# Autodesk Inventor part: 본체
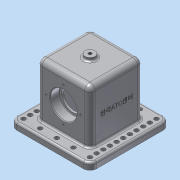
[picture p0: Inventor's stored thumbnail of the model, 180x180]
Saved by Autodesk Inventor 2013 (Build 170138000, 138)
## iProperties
Created: 2018-11
Part Number: 본체
Material: 알루미늄 6061
Document SubType Name: Modeling
Designer: dgall
Density: 2.71 g/cm^3
Mass: 1020.76 g
Surface Area: 777.082 cm^2
Volume: 376.663 cm^3
Author: dgall
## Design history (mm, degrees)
sketch "스케치1"
  geometry: L1 (0, 0)-(80, 0); L2 (80, 0)-(80, 80); L3 (80, 80)-(0, 80); L4 (0, 80)-(0, 0)
  constraints: 8 end point, 2 parallel, 2 perpendicular, 1 horizontal
  dimensions: "d0" = 80 distance of L2.end L3.end
extrude "돌출1" new body sketch "스케치1" distance "d2" = 90; taper "d3" = 0 deg
node "작업 평면1"
sketch "스케치2"
  geometry: L1 (0, 48)-(80, 48); L2 (0, 0)-(0, 90) reference; L3 (80, 0)-(80, 90) reference; L4 (80, 0)-(0, 0) reference; L5 (0, 48)-(0, 68); L6 (0, 68)-(14, 68); L7 (14, 68)-(14, 64.5); L8 (14, 64.5)-(66, 64.5); L9 (66, 64.5)-(66, 68); L10 (66, 68)-(80, 68); L11 (80, 68)-(80, 48)
  constraints: 17 end point, 5 perpendicular, 3 point on line, 1 horizontal
  dimensions: "d4" = 48 distance between parallel lines of L4 L1; "d5" = 40 diameter of L5.end L1; "d6" = 33 diameter of L8 L1; "d7" = 40 diameter of L10.end L1; "d8" = 14 distance of L9.end L10.end; "d9" = 14 distance of L5.end L6.end
revolve "회전1" sketch "스케치2" stored, may be unused: angle "d10" = 90 deg
sketch "스케치3"
  geometry: L1 (-80, 80)-(0, 80) reference; L2 (-80, 0)-(-80, 80) reference; L3 (0, 80)-(0, 0) reference; L4 (-10, 63)-(-10, 17); L5 (-70, 63)-(-70, 17); L6 (-70, 63)-(-10, 63); L7 (-70, 17)-(-10, 17); 6 further points
  constraints: 8 end point, 6 midpoint, 3 parallel, 1 horizontal alignment, 1 perpendicular, 1 vertical alignment
  dimensions: "d91" = 46 distance of L5.start L5.end; "d93" = 60 distance of L5.start L4.start
extrude "돌출2" cut sketch "스케치3" distance "d13" = 80; taper "d14" = 0 deg
node "작업 평면2"
sketch "스케치4"
  geometry: L1 (0, 80)-(0, 0) reference; L2 (80, 80)-(0, 80) reference; C1 r 7.5 at (40, 40); 2 further points
  constraints: 2 midpoint, 1 centre point, 1 horizontal alignment, 1 vertical alignment
  dimensions: "d16" = 15 diameter of C1
extrude "돌출3" join sketch "스케치4" stored distance "d18" = 80; taper "d19" = 0 deg
sketch "스케치5" dims "d20" = 52
  geometry: C1 r 20 at (40, 48) reference; 2 further points
  constraints: 2 vertical alignment, 1 coincident, 2 other
hole "구멍1" sketch "스케치5" at (40, 74) diameter "d21" = 3.242; stored, may be unused: countersink angle "d25" = 90 deg, drill point angle "d27" = 118 deg; dims "d22" = 8, "d23" = 4, "d24" = 2, "d26" = 10
sketch "스케치6" dims "d31" = 52
  geometry: C1 r 20 at (40, -48) reference; 2 further points
  constraints: 2 vertical alignment, 1 coincident, 2 other
hole "구멍2" sketch "스케치6" at (40, -22) diameter "d32" = 3.242; stored, may be unused: countersink angle "d36" = 90 deg, drill point angle "d38" = 118 deg; dims "d33" = 8, "d34" = 4, "d35" = 2, "d37" = 10
sketch "스케치7"
  geometry: C1 r 7.5 at (0, 0) reference; 2 further points
  constraints: 1 coincident
hole "구멍3" sketch "스케치7" at (0, 0) diameter "d42" = 4.917; stored, may be unused: countersink angle "d46" = 90 deg, drill point angle "d48" = 118 deg; dims "d43" = 8, "d44" = 4, "d45" = 2, "d47" = 10
sketch "스케치8"
  geometry: L1 (0, 0)-(-80, 0) reference; L2 (0, 80)-(0, 0) reference; L3 (-80, 80)-(0, 80) reference; L4 (-80, 0)-(-80, 80) reference; L5 (-100, 100)-(20, 100); L6 (20, 100)-(20, -20); L7 (20, -20)-(-100, -20); L8 (-100, -20)-(-100, 100); L9 (-70, 17)-(-70, 63) reference; L10 (-70, 63)-(-10, 63) reference; 4 further points
  constraints: 8 end point, 4 midpoint, 2 parallel, 2 perpendicular, 1 horizontal, 1 horizontal alignment, 1 vertical alignment
  dimensions: "d49" = 120 distance of L5.start L5.end
extrude "돌출4" join sketch "스케치8" distance "d51" = 10; taper "d52" = 0 deg
fillet "모깎기1" dims "d53" = 0.6
fillet "모깎기2" dims "d54" = 3
fillet "모깎기3" dims "d55" = 3
fillet "모깎기4" dims "d56" = 8
fillet "모깎기5" dims "d57" = 8
fillet "모깎기6" dims "d58" = 3
chamfer "모따기1" distance "d59" = 1; stored, may be unused: second distance "d60" = 2, angle "d61" = 45 deg
fillet "모깎기7" dims "d62" = 10
fillet "모깎기8" dims "d63" = 3
sketch "스케치9"
  geometry: L1 (90, -17)-(-10, -17) reference; L2 (-17, -10)-(-17, 90) reference; C1 r 3.3 at (-10, -10); C2 r 3.3 at (-10, 0); C3 r 3.3 at (-10, 10); C4 r 3.3 at (-10, 20); C5 r 3.3 at (-10, 30); C6 r 3.3 at (-10, 40); C7 r 3.3 at (-10, 50); C8 r 3.3 at (-10, 60); C9 r 3.3 at (-10, 70); C10 r 3.3 at (-10, 80); C11 r 3.3 at (-10, 90); C12 r 3.3 at (90, -10); C13 r 3.3 at (90, 0); C14 r 3.3 at (90, 10); C15 r 3.3 at (90, 20); C16 r 3.3 at (90, 30); C17 r 3.3 at (90, 40); C18 r 3.3 at (90, 50); C19 r 3.3 at (90, 60); C20 r 3.3 at (90, 70); C21 r 3.3 at (90, 80); C22 r 3.3 at (90, 90); C23 r 3.3 at (15, -10); C24 r 3.3 at (40, -10); C25 r 3.3 at (65, -10); C26 r 3.3 at (15, 90); C27 r 3.3 at (40, 90); C28 r 3.3 at (65, 90); A1 r 7 centre (-10, -10) between (-17, -10) and (-10, -17) reference; A2 r 7 centre (90, -10) between (90, -17) and (97, -10) reference; 1 further point
  constraints: 28 centre point, 3 horizontal alignment, 2 horizontal, 2 vertical, 1 coincident, 52 other
  dimensions: "d64" = 6.6 diameter of C1; "d68" = 10 distance of C1.centre C2.centre; "d71" = 100 distance of C1.centre C12.centre; "d74" = 6.6 diameter of C23; "d75" = 25 distance of C23.centre A1.centre; "d78" = 25 distance of C23.centre C24.centre; "d81" = 100 distance of C23.centre C26.centre
extrude "돌출5" cut sketch "스케치9" stored distance "d84" = 10; taper "d85" = 0 deg
node "작업 평면3"
sketch "스케치10"
  geometry: L1 (-85, 24.5)-(-85, 39.5) reference; L2 (10, 92)-(10, 82) reference; 3 further points
  constraints: 1 horizontal alignment, 1 midpoint, 1 other
  dimensions: "d87" = 48 horizontal distance of point (-38, 32) L2.start
feature "엠보싱1" sketch "스케치10" dims "d0" = 80, "d7" = 40, "d88" = 0.5, "d89" = 0
fillet "모깎기9" dims "d90" = 3
node "솔리드1"
pattern_circular "원형 패턴1" dims angle "d29" = 360 deg
pattern_circular "원형 패턴2" dims angle "d40" = 360 deg
other parameters: "d15" = 5, "d86" = 20.75
